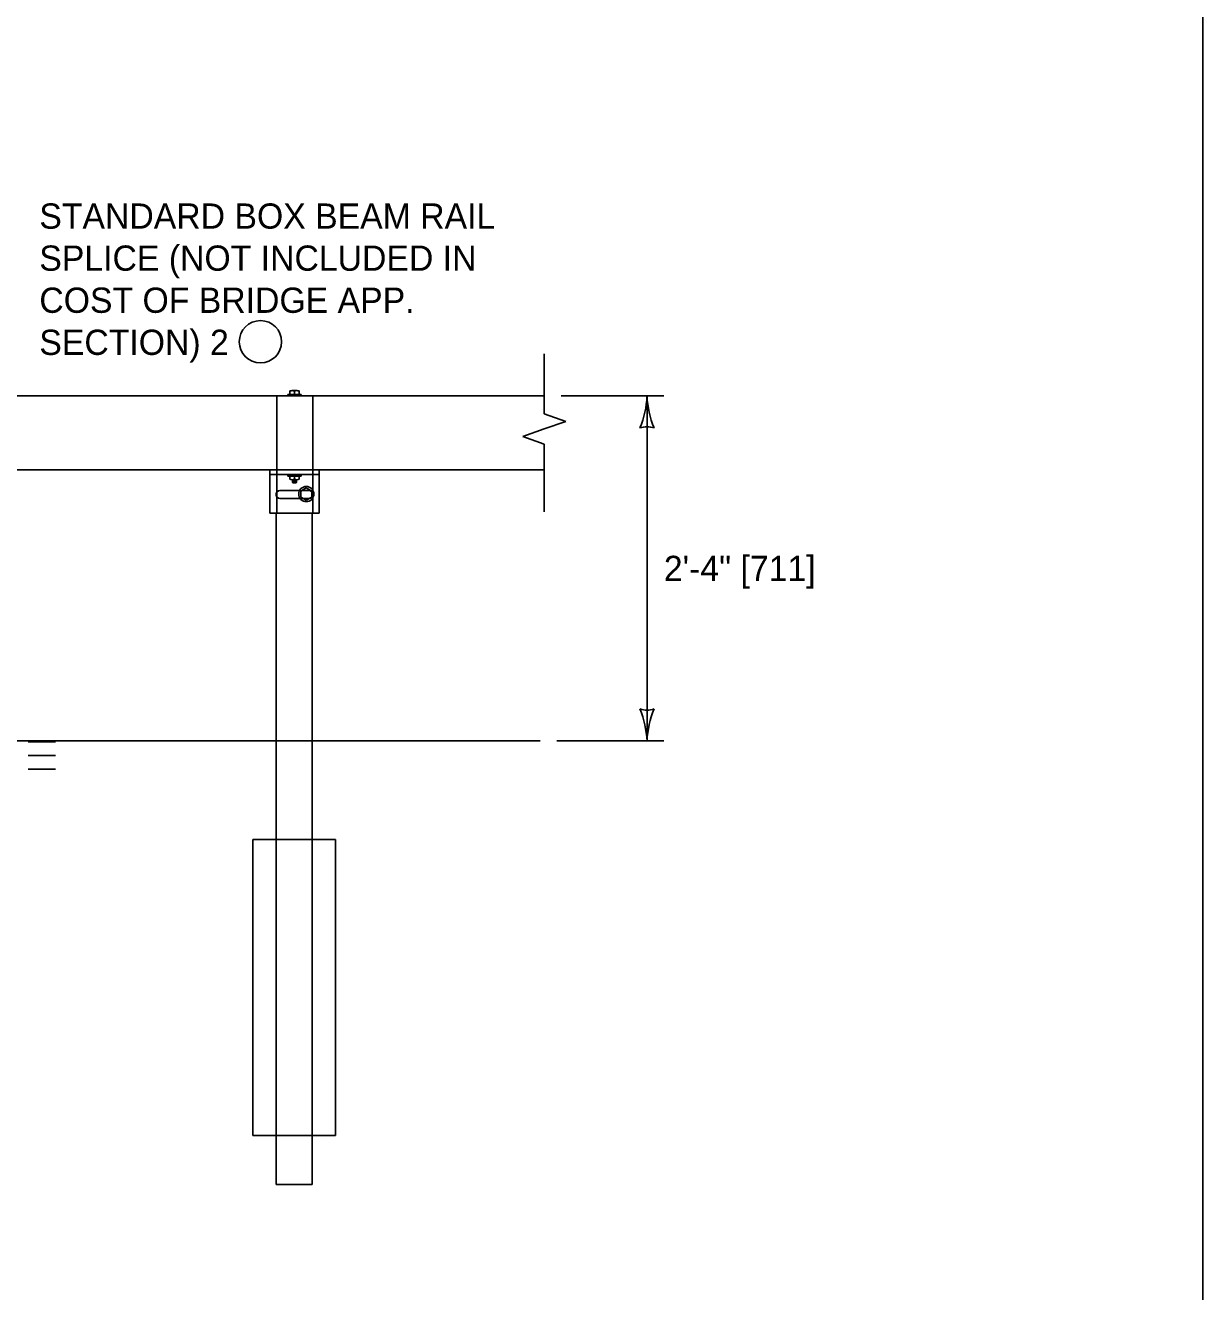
# Model space of a CAD drawing. Extents: x 49983 to 50021, y 49963.5 to 50011.4.
# Drawn here: x 50013.953 to 50016.75, y 49993.158 to 49996.167 of the extents above; entities that cross this region are included whole.
import ezdxf

# ---------------------------------------------------------------- set-up
doc = ezdxf.new("R2010")
doc.units = 0
for name, color, linetype in [('Level 1', 7, 'Continuous'), ('Level 10', 7, 'Continuous'), ('Level 2', 7, 'Continuous'), ('Level 3', 7, 'Continuous'), ('Level 4', 7, 'Continuous'), ('Level 6', 7, 'Continuous')]:
    doc.layers.add(name, color=color, linetype=linetype)

msp = doc.modelspace()

# ---------------------------------------------------------------- linework, layer by layer
at = {"layer": 'Level 1'}
for p, q in [((50013.5013, 49995.2862), (50015.1856, 49995.2862)), ((50014.6497, 49995.2862), (50014.5344, 49995.2862)), ((50014.5763, 49995.2899), (50014.6076, 49995.2899)), ((50014.5763, 49995.2899), (50014.5763, 49995.2862)), ((50014.5811, 49995.2981), (50014.5811, 49995.2899)), ((50014.5866, 49995.2988), (50014.5976, 49995.2988)), ((50014.5921, 49995.2981), (50014.5921, 49995.2899)), ((50014.6031, 49995.2981), (50014.6031, 49995.2899)), ((50014.6076, 49995.2899), (50014.6076, 49995.2862)), ((50013.5013, 49995.1105), (50015.1856, 49995.1105)), ((50014.658, 49995.1105), (50014.5262, 49995.1105)), ((50014.5335, 49995.1105), (50014.5335, 49995.008)), ((50014.6506, 49995.0995), (50014.5335, 49995.0995)), ((50014.5763, 49995.0958), (50014.5763, 49995.0995)), ((50014.5763, 49995.0958), (50014.6077, 49995.0958)), ((50014.581, 49995.0886), (50014.581, 49995.0941)), ((50014.5811, 49995.0958), (50014.5811, 49995.0942)), ((50014.5921, 49995.0941), (50014.5921, 49995.0886)), ((50014.603, 49995.0958), (50014.603, 49995.0942)), ((50014.6032, 49995.0886), (50014.6032, 49995.0941)), ((50014.6077, 49995.0958), (50014.6077, 49995.0995)), ((50014.6506, 49995.1105), (50014.6506, 49995.008)), ((50014.604, 49995.0611), (50014.5569, 49995.0611)), ((50014.5866, 49995.0869), (50014.5976, 49995.0869)), ((50014.587, 49995.0808), (50014.587, 49995.0869)), ((50014.5972, 49995.0808), (50014.587, 49995.0808)), ((50014.587, 49995.0808), (50014.588, 49995.0798)), ((50014.588, 49995.0798), (50014.5962, 49995.0798)), ((50014.5885, 49995.0854), (50014.5957, 49995.0854)), ((50014.5885, 49995.0844), (50014.5957, 49995.0844)), ((50014.5885, 49995.0834), (50014.5957, 49995.0834)), ((50014.5885, 49995.0823), (50014.5957, 49995.0823)), ((50014.5972, 49995.0808), (50014.5962, 49995.0798)), ((50014.5972, 49995.0808), (50014.5972, 49995.0869)), ((50014.6201, 49995.0678), (50014.607, 49995.0601)), ((50014.607, 49995.0601), (50014.607, 49995.0453)), ((50014.6333, 49995.0601), (50014.6201, 49995.0678)), ((50014.6333, 49995.0453), (50014.6333, 49995.0601)), ((50014.6054, 49995.0428), (50014.5574, 49995.0428)), ((50014.607, 49995.0453), (50014.6201, 49995.0382)), ((50014.6201, 49995.0382), (50014.6333, 49995.0453)), ((50014.5335, 49995.008), (50014.6506, 49995.008)), ((50014.5484, 49994.4663), (50014.5484, 49995.008)), ((50014.6342, 49994.4663), (50014.6342, 49995.008)), ((50015.1755, 49994.4663), (50005.1046, 49994.4663)), ((50013.9593, 49994.4643), (50014.0244, 49994.4643)), ((50013.9593, 49994.4318), (50014.0244, 49994.4318)), ((50013.9593, 49994.3993), (50014.0244, 49994.3993))]:
    msp.add_line(p, q, dxfattribs=at)
msp.add_lwpolyline([(49999.3835, 49998.9992), (50016.7501, 49998.9992), (50016.7501, 49987.7988), (49999.3835, 49987.7988)], close=True, dxfattribs=at)
msp.add_circle((50014.6202, 49995.0531), 0.0181, dxfattribs=at)
for centre, radius, start, end in [((50014.5866, 49995.2757), 0.0231, 76.2307, 103.7693), ((50014.5976, 49995.2757), 0.0231, 76.2307, 103.7693), ((50014.5866, 49995.086), 0.00981, 55.616, 124.384), ((50014.5976, 49995.086), 0.00981, 55.616, 124.384), ((50014.5574, 49995.052), 0.00915, 90, 270), ((50014.5866, 49995.0967), 0.00981, 235.616, 304.384), ((50014.5976, 49995.0967), 0.00981, 235.616, 304.384)]:
    msp.add_arc(centre, radius, start, end, dxfattribs=at)
at = {"layer": 'Level 10'}
for p, q in [((50014.5499, 49995.008), (50014.5499, 49995.2862)), ((50014.6357, 49995.008), (50014.6357, 49995.2862)), ((50014.604, 49995.0611), (50014.6268, 49995.0611)), ((50014.6054, 49995.0428), (50014.6268, 49995.0428))]:
    msp.add_line(p, q, dxfattribs=at)
msp.add_arc((50014.6268, 49995.052), 0.00915, 270, 90, dxfattribs=at)
at = {"layer": 'Level 2'}
msp.add_circle((50014.5113, 49995.4149), 0.0503, dxfattribs=at)
at = {"layer": 'Level 3'}
for p, q in [((50015.2256, 49995.2862), (50015.4698, 49995.2862)), ((50015.4298, 49995.2862), (50015.4298, 49994.4663)), ((50015.2155, 49994.4663), (50015.4698, 49994.4663))]:
    msp.add_line(p, q, dxfattribs=at)
for centre, radius, start, end in [((50015.2076, 49995.2954), 0.2223, 337.456, 357.6395), ((50015.6625, 49995.2977), 0.233, 182.8273, 202.0772), ((50015.4298, 49995.158), 0.0548, 72.1388, 107.8612), ((50015.4298, 49994.5945), 0.0548, 252.1388, 287.8612), ((50015.1971, 49994.4548), 0.233, 2.8273, 22.0772), ((50015.6519, 49994.4572), 0.2223, 157.456, 177.6395)]:
    msp.add_arc(centre, radius, start, end, dxfattribs=at)
at = {"layer": 'Level 4'}
for p, q in [((50014.5484, 49994.4663), (50014.5484, 49993.4122)), ((50014.6342, 49993.4122), (50014.6342, 49994.4663)), ((50014.4932, 49993.5293), (50014.4932, 49994.2321)), ((50014.4932, 49994.2321), (50014.6895, 49994.2321)), ((50014.6895, 49994.2321), (50014.6895, 49993.5293)), ((50014.6895, 49993.5293), (50014.4932, 49993.5293)), ((50014.5484, 49993.4122), (50014.6342, 49993.4122))]:
    msp.add_line(p, q, dxfattribs=at)
at = {"layer": 'Level 6'}
for p, q in [((50015.1856, 49995.2438), (50015.1856, 49995.3862)), ((50015.2367, 49995.2257), (50015.1856, 49995.2438)), ((50015.1856, 49995.2077), (50015.2367, 49995.2257)), ((50015.1345, 49995.1895), (50015.1856, 49995.2077)), ((50015.1856, 49995.1714), (50015.1345, 49995.1895)), ((50015.1856, 49995.0105), (50015.1856, 49995.1714))]:
    msp.add_line(p, q, dxfattribs=at)

# ---------------------------------------------------------------- texts
at = {"layer": 'Level 2'}
for s, p in [('STANDARD BOX BEAM RAIL', (50013.9858, 49995.6836)), ('SPLICE (NOT INCLUDED IN', (50013.9858, 49995.5836)), ('COST OF BRIDGE APP.', (50013.9858, 49995.4836)), ('SECTION) 2', (50013.9858, 49995.3836)), ('2\'-4" [711]', (50015.4698, 49994.8463))]:
    msp.add_text(s, height=0.06, dxfattribs=at).set_placement(p)

doc.saveas('drawing.dxf')
